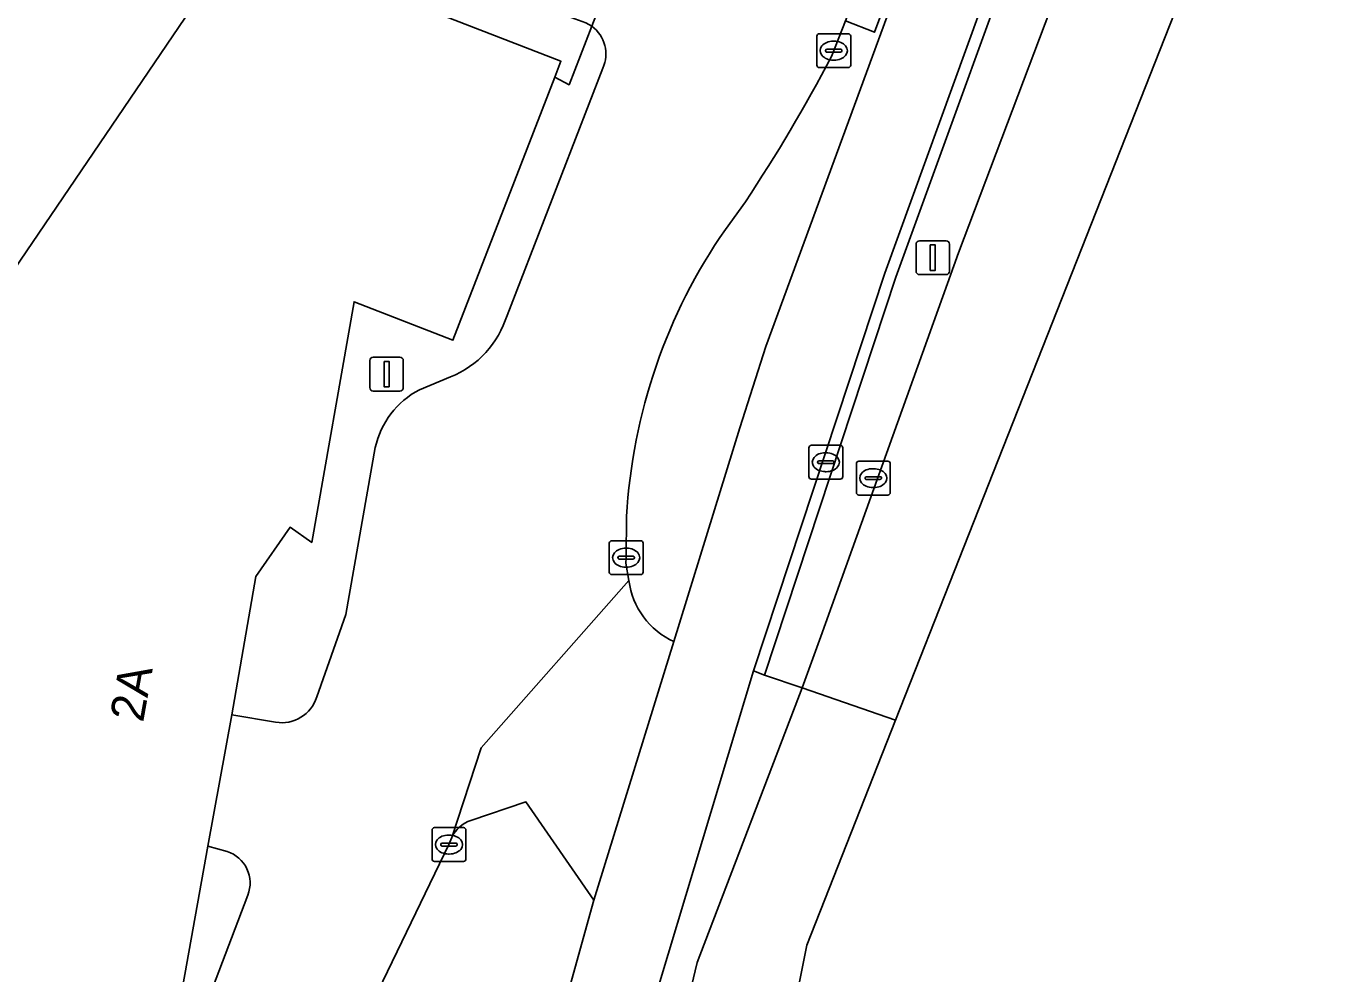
# Model space of a CAD drawing. Extents: x 158132 to 159664, y 385256 to 387218.
# Drawn here: x 159315.62 to 159354.46, y 385360.23 to 385388.22 of the extents above; entities that cross this region are included whole.
import ezdxf

# ---------------------------------------------------------------- set-up
doc = ezdxf.new("R2010")
doc.units = 0
for name, color, linetype in [('IMGEO_Berm_open', 7, 'Continuous'), ('IMGEO_Fietspad_gesloten', 7, 'Continuous'), ('IMGEO_Groenvoorziening', 7, 'Continuous'), ('IMGEO_Kolk', 7, 'Continuous'), ('IMGEO_Lichtmast', 7, 'Continuous'), ('IMGEO_Pand', 7, 'Continuous'), ('IMGEO_Pand_nummerreeks', 7, 'Continuous'), ('IMGEO_Parkeervlak_open', 7, 'Continuous'), ('IMGEO_Rijbaan_lokaal_gesloten', 7, 'Continuous'), ('IMGEO_Rijbaan_lokaal_open', 7, 'Continuous'), ('IMGEO_Voetpad_open', 7, 'Continuous')]:
    doc.layers.add(name, color=color, linetype=linetype)

msp = doc.modelspace()

# ---------------------------------------------------------------- linework, layer by layer
at = {"layer": 'IMGEO_Berm_open'}
for points in [[(159345.777, 385393.089), (159351.028, 385407.265), (159353.797, 385414.59), (159353.565, 385414.672), (159347.632, 385399.1), (159345.432, 385393.179), (159340.99, 385380.922), (159337.107, 385369.181), (159337.434, 385369.055), (159341.31, 385380.813)], [(159343.163, 385381.525), (159347.31, 385392.51), (159345.777, 385393.089), (159341.31, 385380.813), (159337.434, 385369.055), (159338.547, 385368.674), (159339.1, 385370.193)]]:
    msp.add_lwpolyline(points, close=True, dxfattribs=at)
at = {"layer": 'IMGEO_Fietspad_gesloten'}
for points in [[(159361.943, 385442.748), (159360.709, 385440.175), (159358.106, 385434.226), (159357.59, 385432.845), (159356.374, 385429.574), (159355.596, 385427.481), (159353.478, 385421.785), (159352.728, 385419.768), (159351.089, 385415.359), (159344.788, 385398.561), (159341.578, 385389.943), (159337.469, 385378.764), (159336.71, 385376.358), (159334.755, 385370.041), (159332.393, 385362.406), (159326.704, 385341.948)], [(159334.093, 385359.173), (159337.107, 385369.181), (159340.99, 385380.922), (159345.432, 385393.179), (159347.632, 385399.1), (159353.565, 385414.672), (159359.21, 385429.735), (159360.646, 385433.458), (159361.491, 385435.528), (159364.497, 385441.803)]]:
    msp.add_lwpolyline(points, dxfattribs=at)
at = {"layer": 'IMGEO_Groenvoorziening'}
for points in [[(159336.71, 385376.358), (159337.469, 385378.764), (159341.578, 385389.943), (159341.407, 385389.974), (159340.685, 385388.042), (159339.823, 385388.381), (159339.41, 385387.323)], [(159336.869, 385383.033), (159336.278, 385382.216)], [(159334.755, 385370.041), (159336.71, 385376.358)], [(159333.359, 385373.735), (159333.346, 385372.521), (159333.341, 385372.36), (159333.426, 385371.844)], [(159321.848, 385338.844), (159325.605, 385338.172), (159326.704, 385341.948), (159332.393, 385362.406), (159330.382, 385365.305), (159328.758, 385364.759)], [(159328.193, 385364.252), (159328.108, 385364.046), (159322.815, 385353.097), (159323.253, 385352.79), (159316.979, 385343.527), (159319.018, 385342.265), (159314.105, 385331.133), (159288.431, 385342.139)]]:
    msp.add_lwpolyline(points, dxfattribs=at)
for centre, radius, start, end in [((159296.758, 385409.689), 48.16, 326.3941, 332.3287), ((159349.802, 385372.818), 16.469, 145.2057, 176.8093), ((159335.731, 385372.151), 2.325, 187.598, 245.1902), ((159329.067, 385363.846), 0.964, 108.7187, 155.0875)]:
    msp.add_arc(centre, radius, start, end, dxfattribs=at)
at = {"layer": 'IMGEO_Kolk'}
for p, q in [((159338.98, 385387.075), (159338.98, 385387.927)), ((159339.055, 385388.001), (159339.907, 385388.001)), ((159339.468, 385387.781), (159339.493, 385387.781)), ((159339.981, 385387.927), (159339.981, 385387.075)), ((159339.239, 385387.495), (159339.239, 385387.507)), ((159339.677, 385387.458), (159339.279, 385387.458)), ((159339.282, 385387.544), (159339.68, 385387.544)), ((159339.723, 385387.507), (159339.723, 385387.495)), ((159339.907, 385387.001), (159339.055, 385387.001)), ((159339.491, 385387.221), (159339.466, 385387.221)), ((159338.745, 385374.916), (159338.745, 385375.768)), ((159338.82, 385375.842), (159339.672, 385375.842)), ((159339.746, 385375.768), (159339.746, 385374.916)), ((159339.004, 385375.336), (159339.004, 385375.348)), ((159339.047, 385375.385), (159339.445, 385375.385)), ((159339.233, 385375.622), (159339.258, 385375.622)), ((159339.488, 385375.348), (159339.488, 385375.336)), ((159340.223, 385375.371), (159341.075, 385375.371)), ((159339.442, 385375.299), (159339.044, 385375.299)), ((159339.256, 385375.062), (159339.231, 385375.062)), ((159340.148, 385374.445), (159340.148, 385375.297)), ((159340.636, 385375.151), (159340.661, 385375.151)), ((159341.149, 385375.297), (159341.149, 385374.445)), ((159339.672, 385374.842), (159338.82, 385374.842)), ((159340.407, 385374.865), (159340.407, 385374.877)), ((159340.845, 385374.828), (159340.447, 385374.828)), ((159340.45, 385374.914), (159340.848, 385374.914)), ((159340.659, 385374.591), (159340.634, 385374.591)), ((159340.891, 385374.877), (159340.891, 385374.865)), ((159341.075, 385374.371), (159340.223, 385374.371)), ((159332.921, 385373.021), (159333.773, 385373.021)), ((159332.846, 385372.095), (159332.846, 385372.947)), ((159333.334, 385372.801), (159333.359, 385372.801)), ((159333.847, 385372.947), (159333.847, 385372.095)), ((159333.105, 385372.515), (159333.105, 385372.527)), ((159333.543, 385372.478), (159333.145, 385372.478)), ((159333.148, 385372.564), (159333.546, 385372.564)), ((159333.357, 385372.241), (159333.332, 385372.241)), ((159333.589, 385372.527), (159333.589, 385372.515)), ((159333.773, 385372.021), (159332.921, 385372.021)), ((159327.684, 385364.546), (159328.536, 385364.546)), ((159327.609, 385363.62), (159327.609, 385364.472)), ((159327.911, 385364.089), (159328.309, 385364.089)), ((159328.097, 385364.326), (159328.122, 385364.326)), ((159328.61, 385364.472), (159328.61, 385363.62)), ((159327.868, 385364.04), (159327.868, 385364.052)), ((159328.306, 385364.003), (159327.908, 385364.003)), ((159328.12, 385363.766), (159328.095, 385363.766)), ((159328.352, 385364.052), (159328.352, 385364.04)), ((159328.536, 385363.546), (159327.684, 385363.546))]:
    msp.add_line(p, q, dxfattribs=at)
for points in [[(159338.98, 385387.075), (159338.98, 385387.927)], [(159339.055, 385388.001), (159339.907, 385388.001)], [(159339.981, 385387.927), (159339.981, 385387.075)], [(159339.907, 385387.001), (159339.055, 385387.001)], [(159338.745, 385374.916), (159338.745, 385375.768)], [(159338.82, 385375.842), (159339.672, 385375.842)], [(159339.746, 385375.768), (159339.746, 385374.916)], [(159340.223, 385375.371), (159341.075, 385375.371)], [(159340.148, 385374.445), (159340.148, 385375.297)], [(159341.149, 385375.297), (159341.149, 385374.445)], [(159339.672, 385374.842), (159338.82, 385374.842)], [(159341.075, 385374.371), (159340.223, 385374.371)], [(159332.921, 385373.021), (159333.773, 385373.021)], [(159332.846, 385372.095), (159332.846, 385372.947)], [(159333.847, 385372.947), (159333.847, 385372.095)], [(159333.773, 385372.021), (159332.921, 385372.021)], [(159327.684, 385364.546), (159328.536, 385364.546)], [(159327.609, 385363.62), (159327.609, 385364.472)], [(159328.61, 385364.472), (159328.61, 385363.62)], [(159328.536, 385363.546), (159327.684, 385363.546)]]:
    msp.add_lwpolyline(points, dxfattribs=at)
for centre, radius, start, end in [((159339.057, 385387.925), 0.0765, 91.552, 178.448), ((159339.057, 385387.925), 0.0765, 91.552, 178.448), ((159339.905, 385387.925), 0.0765, 1.552, 88.448), ((159339.905, 385387.925), 0.0765, 1.552, 88.448), ((159339.279, 385387.504), 0.0403, 85.8775, 175.7526), ((159339.276, 385387.494), 0.0366, 178.938, 274.7102), ((159339.68, 385387.501), 0.043, 264.8664, 352.4533), ((159339.684, 385387.506), 0.0386, 1.7309, 96.639), ((159339.057, 385387.077), 0.0765, 181.552, 268.448), ((159339.057, 385387.077), 0.0765, 181.552, 268.448), ((159339.905, 385387.077), 0.0765, 271.552, 358.448), ((159339.905, 385387.077), 0.0765, 271.552, 358.448), ((159338.822, 385375.766), 0.0765, 91.552, 178.448), ((159338.822, 385375.766), 0.0765, 91.552, 178.448), ((159339.67, 385375.766), 0.0765, 1.552, 88.448), ((159339.67, 385375.766), 0.0765, 1.552, 88.448), ((159339.044, 385375.345), 0.0403, 85.8775, 175.7526), ((159339.449, 385375.347), 0.0386, 1.7309, 96.639), ((159340.225, 385375.295), 0.0765, 91.552, 178.448), ((159340.225, 385375.295), 0.0765, 91.552, 178.448), ((159341.073, 385375.295), 0.0765, 1.552, 88.448), ((159341.073, 385375.295), 0.0765, 1.552, 88.448), ((159339.041, 385375.335), 0.0366, 178.938, 274.7102), ((159339.445, 385375.342), 0.043, 264.8664, 352.4533), ((159338.822, 385374.918), 0.0765, 181.552, 268.448), ((159338.822, 385374.918), 0.0765, 181.552, 268.448), ((159339.67, 385374.918), 0.0765, 271.552, 358.448), ((159339.67, 385374.918), 0.0765, 271.552, 358.448), ((159340.447, 385374.874), 0.0403, 85.8775, 175.7526), ((159340.444, 385374.864), 0.0366, 178.938, 274.7102), ((159340.848, 385374.871), 0.043, 264.8664, 352.4533), ((159340.852, 385374.876), 0.0386, 1.7309, 96.639), ((159340.225, 385374.447), 0.0765, 181.552, 268.448), ((159340.225, 385374.447), 0.0765, 181.552, 268.448), ((159341.073, 385374.447), 0.0765, 271.552, 358.448), ((159341.073, 385374.447), 0.0765, 271.552, 358.448), ((159332.923, 385372.945), 0.0765, 91.552, 178.448), ((159332.923, 385372.945), 0.0765, 91.552, 178.448), ((159333.771, 385372.945), 0.0765, 1.552, 88.448), ((159333.771, 385372.945), 0.0765, 1.552, 88.448), ((159333.145, 385372.524), 0.0403, 85.8775, 175.7526), ((159333.142, 385372.514), 0.0366, 178.938, 274.7102), ((159333.546, 385372.521), 0.043, 264.8664, 352.4533), ((159333.55, 385372.526), 0.0386, 1.7309, 96.639), ((159332.923, 385372.097), 0.0765, 181.552, 268.448), ((159332.923, 385372.097), 0.0765, 181.552, 268.448), ((159333.771, 385372.097), 0.0765, 271.552, 358.448), ((159333.771, 385372.097), 0.0765, 271.552, 358.448), ((159327.686, 385364.47), 0.0765, 91.552, 178.448), ((159327.686, 385364.47), 0.0765, 91.552, 178.448), ((159328.534, 385364.47), 0.0765, 1.552, 88.448), ((159328.534, 385364.47), 0.0765, 1.552, 88.448), ((159327.908, 385364.049), 0.0403, 85.8775, 175.7526), ((159328.313, 385364.051), 0.0386, 1.7309, 96.639), ((159327.905, 385364.039), 0.0366, 178.938, 274.7102), ((159328.309, 385364.046), 0.043, 264.8664, 352.4533), ((159327.686, 385363.622), 0.0765, 181.552, 268.448), ((159327.686, 385363.622), 0.0765, 181.552, 268.448), ((159328.534, 385363.622), 0.0765, 271.552, 358.448), ((159328.534, 385363.622), 0.0765, 271.552, 358.448)]:
    msp.add_arc(centre, radius, start, end, dxfattribs=at)
for centre, major_axis, ratio, start_param, end_param in [((159339.467, 385387.501), (-0.387, 0.002), 0.722429, 4.712389, 7.853982), ((159339.492, 385387.501), (-0.39, 0.002), 0.717154, 1.570796, 4.712389), ((159339.232, 385375.342), (-0.387, 0.002), 0.722429, 4.712389, 7.853982), ((159339.257, 385375.342), (-0.39, 0.002), 0.717154, 1.570796, 4.712389), ((159340.635, 385374.871), (-0.387, 0.002), 0.722429, 4.712389, 7.853982), ((159340.66, 385374.871), (-0.39, 0.002), 0.717154, 1.570796, 4.712389), ((159333.333, 385372.521), (-0.387, 0.002), 0.722429, 4.712389, 7.853982), ((159333.358, 385372.521), (-0.39, 0.002), 0.717154, 1.570796, 4.712389), ((159328.096, 385364.046), (-0.387, 0.002), 0.722429, 4.712389, 7.853982), ((159328.121, 385364.046), (-0.39, 0.002), 0.717154, 1.570796, 4.712389)]:
    msp.add_ellipse(centre, major_axis=major_axis, ratio=ratio, start_param=start_param, end_param=end_param, dxfattribs=at)
at = {"layer": 'IMGEO_Lichtmast'}
for p, q in [((159341.911, 385380.984), (159341.911, 385381.784)), ((159341.911, 385381.784), (159341.911, 385380.984)), ((159342.011, 385381.884), (159342.801, 385381.884)), ((159342.801, 385381.884), (159342.011, 385381.884)), ((159342.901, 385381.784), (159342.901, 385380.984)), ((159342.901, 385380.984), (159342.901, 385381.784)), ((159342.801, 385380.884), (159342.011, 385380.884)), ((159342.011, 385380.884), (159342.801, 385380.884)), ((159325.771, 385377.545), (159325.771, 385378.345)), ((159325.771, 385378.345), (159325.771, 385377.545)), ((159325.871, 385378.445), (159326.661, 385378.445)), ((159326.661, 385378.445), (159325.871, 385378.445)), ((159326.761, 385378.345), (159326.761, 385377.545)), ((159326.761, 385377.545), (159326.761, 385378.345)), ((159326.661, 385377.445), (159325.871, 385377.445)), ((159325.871, 385377.445), (159326.661, 385377.445))]:
    msp.add_line(p, q, dxfattribs=at)
for points in [[(159342.331, 385381.759), (159342.481, 385381.759), (159342.481, 385381.009), (159342.331, 385381.009), (159342.331, 385381.759)], [(159326.191, 385378.32), (159326.341, 385378.32), (159326.341, 385377.57), (159326.191, 385377.57), (159326.191, 385378.32)]]:
    msp.add_lwpolyline(points, dxfattribs=at)
for centre, start, end in [((159342.011, 385381.784), 90, 180), ((159342.011, 385381.784), 90, 180), ((159342.801, 385381.784), 0, 90), ((159342.801, 385381.784), 360, 90), ((159342.011, 385380.984), 180, 270), ((159342.011, 385380.984), 180, 270), ((159342.801, 385380.984), 270, 0), ((159342.801, 385380.984), 270, 0), ((159325.871, 385378.345), 90, 180), ((159325.871, 385378.345), 90, 180), ((159326.661, 385378.345), 0, 90), ((159326.661, 385378.345), 360, 90), ((159325.871, 385377.545), 180, 270), ((159325.871, 385377.545), 180, 270), ((159326.661, 385377.545), 270, 0), ((159326.661, 385377.545), 270, 0)]:
    msp.add_arc(centre, 0.1, start, end, dxfattribs=at)
at = {"layer": 'IMGEO_Pand'}
msp.add_lwpolyline([(159325.306, 385380.08), (159328.225, 385378.947), (159331.236, 385386.718), (159331.419, 385387.189), (159323.931, 385390.09), (159321.933, 385390.864), (159311.29, 385375.202), (159308.981, 385362.497), (159318.908, 385355.721), (159314.231, 385348.803), (159312.454, 385348.445), (159311.61, 385347.185), (159316.979, 385343.527), (159323.253, 385352.79), (159322.815, 385353.097), (159319.544, 385355.325), (159319.436, 385355.372), (159320.981, 385364.001), (159321.69, 385367.879), (159322.404, 385371.963), (159323.416, 385373.419), (159324.057, 385372.971)], close=True, dxfattribs=at)
at = {"layer": 'IMGEO_Parkeervlak_open'}
msp.add_lwpolyline([(159311.29, 385375.202), (159321.933, 385390.864), (159321.873, 385391.275), (159321.735, 385391.347), (159317.298, 385393.677), (159303.909, 385374.42), (159298.339, 385365.763), (159294.275, 385359.825), (159287.727, 385350.434), (159284.124, 385343.986), (159288.431, 385342.139), (159314.105, 385331.133), (159319.018, 385342.265), (159316.979, 385343.527), (159311.61, 385347.185), (159312.454, 385348.445), (159314.231, 385348.803), (159318.908, 385355.721), (159308.981, 385362.497)], close=True, dxfattribs=at)
for points in [[(159339.41, 385387.323), (159339.823, 385388.381), (159340.567, 385390.319), (159340.92, 385391.221), (159340.759, 385391.283), (159340.651, 385391.005), (159334.353, 385393.445), (159332.33, 385388.22)], [(159332.654, 385386.979), (159329.826, 385379.678)], [(159336.278, 385382.216), (159336.869, 385383.033)], [(159328.155, 385377.86), (159327.237, 385377.483)], [(159325.93, 385375.772), (159325.066, 385370.846), (159324.203, 385368.408)], [(159322.165, 385362.553), (159319.436, 385355.372), (159319.544, 385355.325), (159322.815, 385353.097), (159328.108, 385364.046), (159328.193, 385364.252), (159329.057, 385366.903), (159333.426, 385371.844), (159333.341, 385372.36), (159333.346, 385372.521), (159333.359, 385373.735)], [(159333.426, 385371.844), (159329.057, 385366.903), (159328.193, 385364.252)], [(159328.758, 385364.759), (159330.382, 385365.305), (159332.393, 385362.406), (159334.755, 385370.041)], [(159322.988, 385367.659), (159321.69, 385367.879), (159320.981, 385364.001), (159321.558, 385363.84)]]:
    msp.add_lwpolyline(points, dxfattribs=at)
for centre, radius, start, end in [((159331.741, 385387.403), 1.007, 335.0854, 54.1789), ((159296.758, 385409.689), 48.16, 326.3941, 332.3287), ((159349.802, 385372.818), 16.469, 145.2057, 176.8093), ((159327.073, 385380.532), 2.883, 292.0527, 342.7725), ((159328.433, 385375.215), 2.564, 117.8029, 167.4461), ((159335.731, 385372.151), 2.325, 187.598, 245.1902), ((159323.163, 385368.735), 1.09, 260.7668, 342.5376), ((159329.067, 385363.846), 0.964, 108.7187, 155.0875), ((159321.26, 385362.913), 0.974, 338.3143, 72.1865)]:
    msp.add_arc(centre, radius, start, end, dxfattribs=at)
at = {"layer": 'IMGEO_Rijbaan_lokaal_gesloten'}
for points in [[(159427.275, 385538.785), (159415.675, 385521.795), (159405.1, 385505.382), (159401.845, 385500), (159395.51, 385489.524), (159384.114, 385470.04), (159374.834, 385453.308), (159373.174, 385450.315), (159370.193, 385444.779), (159364.849, 385434.341), (159363.647, 385431.819), (159355.411, 385412.134), (159349.126, 385397.095), (159347.925, 385394.089), (159347.31, 385392.51), (159343.163, 385381.525), (159339.1, 385370.193), (159338.547, 385368.674), (159341.306, 385367.718), (159341.306, 385367.718), (159367.495, 385434.082), (159381.181, 385462.724), (159429.52, 385536.377)], [(159330.36, 385319.44), (159338.683, 385361.07), (159341.306, 385367.718), (159341.306, 385367.718), (159338.547, 385368.674), (159335.444, 385360.564), (159335.053, 385358.921)]]:
    msp.add_lwpolyline(points, dxfattribs=at)
at = {"layer": 'IMGEO_Rijbaan_lokaal_open'}
for points in [[(159341.407, 385389.974), (159340.567, 385390.319), (159339.823, 385388.381), (159340.685, 385388.042)], [(159338.547, 385368.674), (159337.434, 385369.055), (159337.107, 385369.181), (159334.093, 385359.173), (159335.053, 385358.921), (159335.444, 385360.564)]]:
    msp.add_lwpolyline(points, close=True, dxfattribs=at)
at = {"layer": 'IMGEO_Voetpad_open'}
msp.add_lwpolyline([(159323.931, 385390.09), (159331.419, 385387.189), (159331.236, 385386.718), (159331.662, 385386.493), (159332.33, 385388.22), (159332.152, 385388.323), (159328.036, 385389.828), (159327.867, 385389.359), (159324.253, 385390.924)], close=True, dxfattribs=at)
for points in [[(159332.33, 385388.22), (159331.662, 385386.493), (159331.236, 385386.718), (159328.225, 385378.947), (159325.306, 385380.08), (159324.057, 385372.971), (159323.416, 385373.419), (159322.404, 385371.963), (159321.69, 385367.879), (159322.988, 385367.659)], [(159329.826, 385379.678), (159332.654, 385386.979)], [(159327.237, 385377.483), (159328.155, 385377.86)], [(159324.203, 385368.408), (159325.066, 385370.846), (159325.93, 385375.772)], [(159321.558, 385363.84), (159320.981, 385364.001), (159319.436, 385355.372), (159322.165, 385362.553)]]:
    msp.add_lwpolyline(points, dxfattribs=at)
for centre, radius, start, end in [((159331.741, 385387.403), 1.007, 335.0854, 54.1789), ((159327.073, 385380.532), 2.883, 292.0527, 342.7725), ((159328.433, 385375.215), 2.564, 117.8029, 167.4461), ((159323.163, 385368.735), 1.09, 260.7668, 342.5376), ((159321.26, 385362.913), 0.974, 338.3143, 72.1865)]:
    msp.add_arc(centre, radius, start, end, dxfattribs=at)

# ---------------------------------------------------------------- texts
at = {"layer": 'IMGEO_Pand_nummerreeks'}
msp.add_text('2A', height=1, rotation=79.8646, dxfattribs=at).set_placement((159319.071, 385367.633))

doc.saveas('drawing.dxf')
